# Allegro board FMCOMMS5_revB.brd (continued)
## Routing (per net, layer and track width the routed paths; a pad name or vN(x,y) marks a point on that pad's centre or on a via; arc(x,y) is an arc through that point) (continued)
RESET_A: length 113.7
  TOP w0.203: R103.2 26.49,116.87 v2(26.47,116.89)
  TOP w0.508: P401.C23 v1(86.88,107.68)
  L5_SIG w0.124: P101.25 73.17,117.4 71.85,118.72 71.85,120.62 69.38,123.1 69.03,123.1 65.16,126.97 64.19,126.97 63.74,127.42 63.74,128.52 61.62,130.63 51.69,130.63 51.53,130.47 35.09,130.47 32.91,128.3 25.78,128.3 18.41,120.93 18.41,119.63 18.42,119.62 18.42,111.49 18.96,110.96 19.74,110.96 21.47,109.23 23.82,109.23 24.55,109.96 24.55,110.41 24.43,110.52 24.43,110.81 24.55,110.92 24.55,111.54 24.43,111.65 24.43,111.94 25.23,112.74 25.23,113.88 25.71,114.36 25.71,114.9 25.56,115.05 25.56,115.5 26.25,116.18 26.25,116.67 v2(26.47,116.89)
  L6_SIG w0.124: P101.25 73.87,115.99 80.16,115.99 81.5,114.64 83.55,114.64 86.34,111.85 86.34,108.24 86.88,107.71 v1(86.88,107.68)
  BOTTOM w0.254: v2(26.47,116.89) U101.K5
RESET_B: length 141.8
  TOP w0.394: R203.2 21.56,27.3 v2(21.54,27.28)
  TOP w0.508: P402.G30 v1(80.04,47.21)
  L5_SIG w0.124: v1(80.04,47.21) 79.77,47.48 75.78,47.48 75.03,46.73 P201.25 73.43,47.39 72.2,48.62 72.2,51.47 69.65,54.02 58.78,54.02 55.18,57.62 23.01,57.62 16.21,50.81 13.27,50.81 12.43,49.97 12.43,42.7 9.25,39.53 9.25,30.65 10.6,29.3 10.6,27.52 13.27,24.85 13.27,23.66 17.75,19.18 19.45,19.18 19.88,18.75 27.84,18.75 29.73,20.64 29.73,24.1 28.47,25.36 28.03,25.36 27.91,25.24 27.62,25.24 27.51,25.36 26.89,25.36 26.78,25.24 26.36,25.24 25.56,26.04 24.39,26.04 23.95,26.49 23.58,26.49 23.53,26.45 23.46,26.37 23.1,26.37 22.19,27.28 v2(21.54,27.28)
  BOTTOM w0.254: U201.K5 v2(21.54,27.28)
RX1A_A: length 10.9
  BOTTOM w0.394: J111.1 35.56,135.21 arc(35.18,133.3) 34.1,131.69 31.81,129.39 T106.3
RX1A_B: length 10.2
  BOTTOM w0.394: J210.1 5.18,35.56 arc(6.03,35.39) 6.74,34.91 9.04,32.62 T205.3
RX1A_N_A: length 5.2
  BOTTOM w0.203: C106.2 28.14,123.32 arc(27.81,123.26) 27.54,123.08 27.18,122.72 arc(26.8,122.16) 26.68,121.5 arc(26.54,120.56) 26.13,119.69 25.96,119.52 arc(25.92,119.46) 25.9,119.38 U101.M2
RX1A_N_B: length 5.2
  BOTTOM w0.203: U201.M2 19.05,26.71 arc(18.97,26.73) 18.91,26.77 18.74,26.94 arc(17.88,27.35) 16.93,27.49 16.93,27.49 arc(16.27,27.62) 15.71,27.99 15.36,28.35 arc(15.17,28.62) 15.11,28.95 C208.2
RX1A_P_A: length 5.2
  BOTTOM w0.203: C107.2 27.53,123.89 arc(27.48,123.6) 27.31,123.35 26.93,122.97 arc(26.48,122.29) 26.32,121.5 arc(26.2,120.67) 25.85,119.92 25.71,119.78 arc(25.64,119.73) 25.57,119.72 U101.M1
RX1A_P_B: length 5.2
  BOTTOM w0.203: C209.2 14.54,28.34 arc(14.83,28.29) 15.08,28.12 15.46,27.74 arc(16.14,27.29) 16.93,27.13 arc(17.76,27.01) 18.51,26.66 18.66,26.52 arc(18.7,26.45) 18.72,26.38 U201.M1
RX1B_A: length 6.7
  BOTTOM w0.394: J103.1 17.78,132.09 C146.2 L106.1
RX1B_B: length 6.7
  BOTTOM w0.394: J203.1 6.88,17.78 C246.2 L206.1
RX1B_N_A: length 3
  BOTTOM w0.203: U101.J1 23.41,118.02 arc(23.33,118.03) 23.26,118.08 23.03,118.31 arc(22.95,118.43) 22.92,118.57 22.92,119.06 arc(22.87,119.32) 22.73,119.53 22.6,119.66 22.6,119.66 arc(22.38,120) C128.2
RX1B_N_B: length 3
  BOTTOM w0.203: U201.J1 20.41,24.22 arc(20.4,24.14) 20.35,24.08 20.12,23.84 arc(20,23.76) 19.86,23.73 19.37,23.73 arc(19.11,23.68) 18.9,23.54 18.77,23.41 arc(18.43,23.19) C228.2
RX1B_P_A: length 3
  BOTTOM w0.203: U101.H1 23.07,117.68 arc(23.06,117.76) 23.01,117.83 22.78,118.06 arc(22.62,118.3) 22.57,118.57 22.57,119.06 arc(22.54,119.18) 22.48,119.28 22.35,119.41 arc(22.01,119.63) C129.2
RX1B_P_B: length 3
  BOTTOM w0.203: U201.H1 20.75,23.88 arc(20.67,23.87) 20.6,23.82 20.37,23.59 arc(20.13,23.43) 19.86,23.38 19.37,23.38 arc(19.25,23.35) 19.15,23.29 19.02,23.16 arc(18.8,22.82) C229.2
RX1C_A: length 66.4
  TOP w0.394: v3(14.18,127.14) 14.41,127.37 15.07,127.37 T103.3
  L6_SIG w0.124: v3(14.18,127.14) 14.18,126.23 13.15,125.2 13.15,113.88 13.32,113.71 13.32,109.45 16.2,106.58 16.2,100.53 16.52,100.21 16.52,79.12 17.16,78.48 17.16,74.81 17.79,74.18 17.79,72.22 19.78,70.24 19.78,67.11 v3(20.33,66.56)
  BOTTOM w0.394: C351.2 v3(20.33,66.56)
RX1C_B: length 66.4
  TOP w0.394: T203.3 12.63,17.45 12.65,17.45 v3(12.75,17.55)
  L6_SIG w0.124: v3(18.37,66.61) 17.76,67.22 9.28,67.22 8.16,66.1 8.16,59.78 9.18,58.76 11.97,58.76 12.71,58.03 12.71,39.79 12.25,39.33 12.25,37.64 11.77,37.15 11.77,33.59 11.23,33.06 11.23,30.9 11.92,30.21 11.92,18.38 v3(12.75,17.55)
  BOTTOM w0.394: C352.2 v3(18.37,66.61)
RX1C_N_A: length 7
  TOP w0.203: C126.2 arc(19.14,121.87) 19.37,121.52 19.48,121.41 19.83,121.06 arc(19.99,120.95) 20.17,120.92 20.78,120.92 arc(21.99,120.68) 23.01,120 23.32,119.69 arc(23.32,119.68) 23.33,119.68 23.62,119.42 23.63,119.4 arc(23.84,119.26) v2(24.09,119.21)
  BOTTOM w0.254: v2(24.09,119.21) 24.15,119.15 U101.L1
RX1C_N_B: length 7
  TOP w0.203: v2(19.22,24.9) arc(19.17,24.65) 19.03,24.44 19.01,24.43 18.75,24.14 arc(18.75,24.13) 18.74,24.13 18.44,23.82 arc(17.75,22.8) 17.51,21.6 17.51,20.98 arc(17.48,20.8) 17.37,20.64 17.03,20.3 16.91,20.18 arc(16.56,19.95) C226.2
  BOTTOM w0.254: U201.L1 19.28,24.96 v2(19.22,24.9)
RX1C_P_A: length 7
  TOP w0.203: v2(23.63,118.71) arc(23.6,118.87) 23.5,119.01 23.21,119.31 23.09,119.42 arc(23.08,119.43) 23.07,119.44 22.76,119.74 arc(21.85,120.35) 20.78,120.56 20.17,120.56 arc(19.85,120.62) 19.58,120.81 19.23,121.15 19.12,121.27 arc(18.77,121.5) C127.2
  BOTTOM w0.254: v2(23.63,118.71) 23.75,118.58 U101.K1
RX1C_P_B: length 7
  TOP w0.203: v2(19.72,24.44) arc(19.56,24.41) 19.42,24.31 19.13,24.02 19.01,23.9 arc(19,23.89) 18.99,23.88 18.69,23.57 arc(18.08,22.66) 17.87,21.6 17.87,20.98 arc(17.81,20.66) 17.63,20.39 17.28,20.04 17.16,19.93 arc(16.93,19.58) C227.2
  BOTTOM w0.254: U201.K1 19.85,24.56 v2(19.72,24.44)
RX2A_A: length 11.7
  BOTTOM w0.394: T105.3 11.23,105.23 arc(9.25,103.9) 6.92,103.44 J110.1
RX2A_B: length 12.6
  BOTTOM w0.394: J211.1 35.56,6.06 arc(34.95,9.27) 33.21,12.04 T206.3
RX2A_N_A: length 5.2
  BOTTOM w0.203: 14.8,111.3 14.94,111.3 arc(15.23,111.35) 15.48,111.52 15.86,111.9 arc(16.54,112.35) 17.33,112.51 arc(18.15,112.63) 18.91,112.98 19.05,113.12 arc(19.1,113.19) 19.11,113.26 U101.A1
RX2A_N_B: length 5.2
  BOTTOM w0.203: U201.A1 25.17,19.92 arc(25.25,19.91) 25.31,19.86 25.46,19.72 arc(25.8,18.97) 25.92,18.14 arc(26.08,17.35) 26.53,16.67 26.91,16.29 arc(27.08,16.04) 27.14,15.75 C206.2
RX2A_P_A: length 5.2
  BOTTOM w0.203: 15.5,110.59 15.5,110.69 arc(15.57,111.02) 15.75,111.29 16.11,111.65 arc(16.67,112.02) 17.33,112.15 17.33,112.15 arc(18.27,112.29) 19.14,112.7 19.31,112.87 arc(19.37,112.91) 19.45,112.93 U101.A2
RX2A_P_B: length 5.2
  BOTTOM w0.203: U201.A2 25.5,20.26 arc(25.52,20.18) 25.56,20.12 25.73,19.95 arc(26.14,19.08) 26.28,18.14 26.28,18.14 arc(26.41,17.48) 26.78,16.92 27.14,16.56 arc(27.41,16.38) 27.74,16.32 27.84,16.32
RX2B_A: length 6.7
  BOTTOM w0.394: J104.1 6.88,121.22 C151.2 L108.1
RX2B_B: length 6.7
  BOTTOM w0.394: L208.1 C251.2 17.78,6.9 J204.1
RX2B_N_A: length 3
  BOTTOM w0.203: U101.F1 21.71,116.32 arc(21.63,116.34) 21.57,116.38 21.33,116.61 arc(21.1,116.77) 20.82,116.83 20.33,116.83 arc(20.21,116.85) 20.11,116.92 19.99,117.04 arc(19.76,117.38) C130.2
RX2B_N_B: length 3
  BOTTOM w0.203: U201.F1 22.11,22.52 arc(22.09,22.44) 22.05,22.38 21.82,22.15 arc(21.66,21.91) 21.6,21.63 21.6,21.14 arc(21.58,21.02) 21.51,20.92 21.39,20.8 arc(21.05,20.57) C230.2
RX2B_P_A: length 3
  BOTTOM w0.203: U101.E1 21.38,115.99 arc(21.36,116.06) 21.32,116.13 21.32,116.13 21.08,116.36 arc(20.96,116.44) 20.82,116.47 20.33,116.47 arc(20.08,116.52) 19.86,116.67 19.74,116.79 arc(19.4,117.02) C131.2
RX2B_P_B: length 3
  BOTTOM w0.203: U201.E1 22.44,22.19 arc(22.37,22.17) 22.3,22.13 22.3,22.13 22.07,21.89 arc(21.99,21.77) 21.96,21.63 21.96,21.14 arc(21.91,20.89) 21.76,20.67 21.64,20.55 21.64,20.55 arc(21.41,20.21) C231.2
RX_D0_N_A: length 85.4
  TOP w0.203: P401.H8 v1(80,88)
  L5_SIG w0.097: v2(30.43,112.93) 30.43,112.46 33.01,109.88 33.01,108.02 34.84,106.2 34.84,105.28 35.28,104.83 37.51,104.83 38.01,104.33 38.01,97.4 40.33,95.09 40.33,93.58 40.84,93.07 58.53,93.07 58.94,93.48 58.94,97.02 59.22,97.29 63.08,97.29 63.36,97.02 63.36,92.93 63.48,92.8 67.14,92.8 67.26,92.93 67.26,96.72 67.54,97 75.92,97 76.42,96.5 76.42,90.74 77.86,89.3 78.91,89.3 79.53,88.68 79.53,88.47 v1(80,88)
  BOTTOM w0.203: U101.K11 v2(30.43,112.93)
RX_D0_N_B: length 84.2
  TOP w0.203: P402.H8 v1(80,18.04)
  L5_SIG w0.097: v2(25.5,31.24) 25.64,31.24 25.87,31.47 26.33,31.47 27.95,33.09 34.29,33.09 39.7,27.68 45.64,27.68 50.04,23.28 52.29,23.28 52.74,22.83 52.74,20.91 52.87,20.78 54.24,20.78 54.36,20.91 54.36,22.01 54.68,22.33 68.8,22.33 69.36,22.89 69.36,26.95 69.64,27.22 71.21,27.22 71.49,26.95 71.49,23.07 71.59,22.97 73.13,22.97 73.22,23.06 73.22,26.41 73.98,27.18 75.97,27.18 76.47,26.68 76.47,19.97 77.09,19.34 78.93,19.34 79.54,18.73 79.54,18.5 v1(80,18.04)
  BOTTOM w0.203: U201.K11 v2(25.5,31.24)
RX_D0_P_A: length 85.4
  TOP w0.203: P401.H7 v1(78.73,88)
  L5_SIG w0.097: v2(29.86,112.36) 30.17,112.36 32.76,109.78 32.76,107.92 34.58,106.09 34.58,105.17 35.18,104.58 37.4,104.58 37.76,104.22 37.76,97.3 40.07,94.98 40.07,93.47 40.73,92.81 58.64,92.81 59.2,93.37 59.2,96.91 59.32,97.04 62.97,97.04 63.1,96.91 63.1,92.82 63.38,92.54 67.24,92.54 67.52,92.82 67.52,96.62 67.64,96.75 75.82,96.75 76.16,96.4 76.16,90.63 77.75,89.04 78.81,89.04 79.28,88.58 79.28,88.18 79.1,88 v1(78.73,88)
  BOTTOM w0.203: U101.J12 v2(29.86,112.36)
RX_D0_P_B: length 84.2
  TOP w0.203: 79.36,17.41 v1(78.73,18.04)
  L5_SIG w0.097: v2(26.07,30.67) 25.98,30.67 25.85,30.8 25.85,31.09 25.97,31.22 26.43,31.22 28.06,32.84 34.18,32.84 39.6,27.43 45.53,27.43 49.93,23.03 52.19,23.03 52.49,22.72 52.49,20.81 52.77,20.53 54.34,20.53 54.62,20.81 54.62,21.9 54.79,22.07 68.9,22.07 69.61,22.78 69.61,26.84 69.74,26.97 71.11,26.97 71.24,26.84 71.24,22.97 71.48,22.72 73.23,22.72 73.47,22.96 73.47,26.3 74.09,26.92 75.87,26.92 76.21,26.57 76.21,19.86 76.99,19.09 78.82,19.09 79.29,18.62 79.29,18.22 79.11,18.04 v1(78.73,18.04)
  BOTTOM w0.203: U201.J12 v2(26.07,30.67)
RX_D1_N_A: length 85
  TOP w0.203: 80.63,91.17 v1(80,90.54)
  L5_SIG w0.097: v2(29.86,113.49) 29.88,113.51 30.55,113.51 30.86,113.82 31.1,113.82 31.23,113.95 31.23,114.35 31.35,114.48 31.74,114.48 31.87,114.36 31.87,114.21 32.01,114.07 32.99,114.07 34.31,112.75 34.31,107.87 35.11,107.07 38.84,107.07 39.25,106.66 39.25,99.01 41.29,96.97 57.6,96.97 57.73,97.09 57.73,99.17 58.12,99.56 59.67,99.56 59.8,99.68 59.8,100.84 60.04,101.08 62.19,101.08 62.44,100.84 62.44,98.18 62.56,98.05 64.44,98.05 64.56,98.18 64.56,100.6 64.84,100.87 66.93,100.87 67.2,100.6 67.2,98.23 67.3,98.13 75.68,98.13 77.45,96.36 77.45,91.45 78.24,90.67 78.46,90.67 79.23,89.9 79.36,89.9 v1(80,90.54)
  BOTTOM w0.203: U101.K10 v2(29.86,113.49)
RX_D1_N_B: length 84.4
  TOP w0.203: 80.63,21.22 v1(80,20.58)
  L5_SIG w0.097: v2(24.94,30.67) 24.92,30.69 24.92,31.36 24.04,32.23 24.04,32.51 24.36,32.82 24.36,33.8 25.08,34.52 34.74,34.52 40.65,28.61 46,28.61 49.05,25.56 62.21,25.56 62.53,25.23 62.53,23.25 62.63,23.15 64.06,23.15 64.15,23.25 64.15,25.81 64.43,26.09 66.01,26.09 66.28,25.81 66.28,23.25 66.38,23.15 67.81,23.15 67.9,23.25 67.9,28.37 68.15,28.61 75.45,28.61 77.7,26.36 77.7,21.26 78.25,20.71 78.48,20.71 79.24,19.95 79.36,19.95 v1(80,20.58)
  BOTTOM w0.203: U201.K10 v2(24.94,30.67)
RX_D1_P_A: length 85
  TOP w0.203: 80.63,89.9 v1(80,89.27)
  L5_SIG w0.097: v2(29.3,112.93) 29.53,113.17 30.01,113.17 30.09,113.26 30.77,113.26 30.86,113.17 31.13,113.17 31.78,113.82 32.88,113.82 34.06,112.65 34.06,107.76 35.01,106.81 38.74,106.81 38.99,106.56 38.99,98.91 41.18,96.71 57.71,96.71 57.99,96.99 57.99,99.06 58.22,99.3 59.78,99.3 60.05,99.58 60.05,100.73 60.15,100.83 62.09,100.83 62.18,100.73 62.18,98.07 62.46,97.8 64.54,97.8 64.82,98.07 64.82,100.49 64.95,100.62 66.82,100.62 66.95,100.49 66.95,98.12 67.19,97.88 75.57,97.88 77.2,96.25 77.2,91.35 78.13,90.41 78.36,90.41 79.12,89.65 79.62,89.65 v1(80,89.27)
  BOTTOM w0.203: U101.J11 v2(29.3,112.93)
RX_D1_P_B: length 84.4
  TOP w0.203: 80.63,19.95 v1(80,19.31)
  L5_SIG w0.097: v2(25.5,30.11) 25.27,30.34 25.27,30.82 25.18,30.91 25.18,31.58 25.27,31.67 25.27,31.94 24.61,32.59 24.61,33.69 25.19,34.27 34.63,34.27 40.55,28.36 45.9,28.36 48.94,25.31 62.1,25.31 62.28,25.13 62.28,23.14 62.53,22.9 64.16,22.9 64.41,23.14 64.41,25.7 64.54,25.83 65.9,25.83 66.03,25.7 66.03,23.14 66.27,22.9 67.91,22.9 68.16,23.14 68.16,28.26 68.25,28.36 75.34,28.36 77.45,26.25 77.45,21.15 78.15,20.46 78.37,20.46 79.13,19.69 79.63,19.69 80.01,19.31 v1(80,19.31)
  BOTTOM w0.203: U201.J11 v2(25.5,30.11)
RX_D2_N_A: length 84.8
  TOP w0.203: P401.H11 v1(80,91.81)
  L5_SIG w0.097: v2(29.3,114.06) 29.3,114.66 30.16,115.52 33.86,115.52 35.01,114.37 35.47,113.91 35.47,110.59 35.76,110.3 38.43,110.3 38.82,109.91 38.82,108.21 39.15,107.87 40.77,107.87 41.2,107.44 41.2,100.17 41.5,99.87 54.22,99.87 54.49,99.6 54.49,97.86 54.59,97.76 56.52,97.76 56.62,97.86 56.62,101.64 57.02,102.03 69.52,102.03 69.8,101.75 69.8,98.89 69.93,98.76 72.27,98.76 72.4,98.89 72.4,101.35 72.67,101.63 74.29,101.63 74.57,101.35 74.57,100.45 79.5,95.51 79.5,92.31 v1(80,91.81)
  BOTTOM w0.203: U101.K9 v2(29.3,114.06)
RX_D2_N_B: length 84.3
  TOP w0.203: 79.36,22.49 v1(80,21.85)
  L5_SIG w0.097: v2(24.37,30.11) 23.77,30.11 22.91,30.97 22.91,34.24 24.18,35.5 27.01,35.5 27.21,35.7 35.35,35.7 41.52,29.52 50.15,29.52 50.46,29.21 50.46,26.65 50.56,26.56 63.24,26.56 63.33,26.65 63.33,29.37 63.61,29.64 65.19,29.64 65.46,29.37 65.46,27.2 65.59,27.07 66.95,27.07 67.08,27.2 67.08,29.21 67.4,29.52 71.95,29.52 72.15,29.73 72.15,30.37 72.52,30.74 75.84,30.74 76.81,29.77 76.81,28.26 79.51,25.55 79.51,22.35 79.55,22.31 79.55,22.3 v1(80,21.85)
  BOTTOM w0.203: U201.K9 v2(24.37,30.11)
RX_D2_P_A: length 84.8
  TOP w0.203: P401.H10 v1(78.73,91.81)
  L5_SIG w0.097: v1(78.73,91.81) 78.85,91.81 79.25,92.2 79.25,95.4 74.31,100.34 74.31,101.24 74.18,101.37 72.78,101.37 72.65,101.24 72.65,98.78 72.37,98.51 69.82,98.51 69.55,98.78 69.55,101.65 69.41,101.78 57.12,101.78 56.87,101.53 56.87,97.75 56.63,97.51 54.48,97.51 54.24,97.75 54.24,99.49 54.11,99.62 41.4,99.62 40.95,100.07 40.95,107.34 40.67,107.62 39.05,107.62 38.57,108.1 38.57,109.81 38.33,110.05 35.65,110.05 35.21,110.48 35.21,113.8 34.83,114.19 33.75,115.26 30.96,115.26 29.43,113.73 28.97,113.73 v2(28.73,113.49)
  BOTTOM w0.203: U101.J10 v2(28.73,113.49)
RX_D2_P_B: length 84.3
  TOP w0.203: P402.H10 v1(78.73,21.85)
  L5_SIG w0.097: v1(78.73,21.85) 79.09,21.85 79.26,22.02 79.26,25.45 76.56,28.15 76.56,29.66 75.73,30.49 72.63,30.49 72.41,30.27 72.41,29.62 72.06,29.27 67.5,29.27 67.34,29.11 67.34,27.09 67.06,26.81 65.48,26.81 65.21,27.09 65.21,29.26 65.08,29.39 63.71,29.39 63.59,29.26 63.59,26.55 63.34,26.3 50.46,26.3 50.21,26.55 50.21,29.11 50.05,29.27 41.42,29.27 35.24,35.45 27.31,35.45 27.11,35.25 24.28,35.25 23.17,34.13 23.17,31.78 23.57,31.37 23.57,31.08 23.7,30.95 23.99,30.95 24.12,30.82 24.12,30.65 24.34,30.43 24.51,30.43 24.7,30.24 24.7,29.78 v2(24.94,29.54)
  BOTTOM w0.203: U201.J10 v2(24.94,29.54)
RX_D3_N_A: length 85.4
  TOP w0.203: P401.D12 v1(85.08,93.08)
  L5_SIG w0.097: v2(28.16,115.19) 28.16,114.99 28.26,114.9 28.46,114.9 28.58,115.02 28.58,115.51 29.37,116.29 35.08,116.29 35.48,115.89 35.48,114.99 35.61,114.86 36.69,114.86 36.82,114.99 36.82,116.42 37.1,116.7 39,116.7 39.27,116.42 39.27,110.46 39.46,110.28 43.32,110.28 43.59,110 43.59,104.97 43.72,104.85 47.94,104.85 48.07,104.97 48.07,107.24 48.34,107.52 50.43,107.52 50.71,107.24 50.71,104.91 50.8,104.82 72.28,104.82 77.56,99.54 78.55,99.54 79.34,98.75 79.34,96.82 80.39,95.77 83.99,95.77 84.1,95.65 84.6,95.16 84.6,93.56 v1(85.08,93.08)
  BOTTOM w0.203: U101.K8 v2(28.16,115.19)
RX_D3_N_B: length 85.6
  TOP w0.203: P402.D12 v1(85.08,23.12)
  L5_SIG w0.097: v2(23.24,28.98) 23.36,28.98 23.47,29.08 23.47,29.24 23.32,29.39 22.92,29.39 22.14,30.18 22.14,34.71 24.23,36.79 42.15,36.79 42.9,36.04 42.9,31.42 43.4,30.92 55.76,30.92 55.89,31.05 55.89,32.07 56.25,32.43 71.77,32.43 72.54,33.2 74.27,33.2 74.55,32.93 74.55,31.69 74.77,31.47 76.06,31.47 77.94,29.58 78.57,29.58 79.35,28.8 79.35,26.86 80.4,25.81 84,25.81 84.16,25.65 84.76,25.05 84.76,23.44 v1(85.08,23.12)
  BOTTOM w0.203: U201.K8 v2(23.24,28.98)
RX_D3_P_A: length 85.4
  TOP w0.203: P401.D11 v1(83.81,93.08)
  L5_SIG w0.097: v2(28.16,114.06) 28.16,114.55 28.25,114.65 28.57,114.65 28.84,114.92 28.84,115.4 29.48,116.04 34.98,116.04 35.23,115.79 35.23,114.88 35.51,114.61 36.8,114.61 37.07,114.88 37.07,116.32 37.2,116.44 38.89,116.44 39.02,116.32 39.02,110.36 39.35,110.02 43.21,110.02 43.34,109.9 43.34,104.87 43.61,104.59 48.05,104.59 48.32,104.87 48.32,107.14 48.45,107.26 50.32,107.26 50.45,107.14 50.45,104.81 50.7,104.56 72.17,104.56 77.45,99.28 78.45,99.28 79.09,98.65 79.09,96.71 80.28,95.52 83.88,95.52 83.97,95.43 84.35,95.05 84.35,93.46 83.97,93.08 v1(83.81,93.08)
  BOTTOM w0.203: U101.J9 v2(28.16,114.06)
RX_D3_P_B: length 85.6
  TOP w0.203: 84.44,22.49 v1(83.81,23.12)
  L5_SIG w0.097: v1(83.81,23.12) 84.32,23.12 84.51,23.31 84.51,24.95 83.98,25.47 83.89,25.56 80.29,25.56 79.1,26.76 79.1,28.69 78.46,29.33 77.84,29.33 75.95,31.21 74.66,31.21 74.3,31.58 74.3,32.82 74.17,32.95 72.65,32.95 71.88,32.18 56.35,32.18 56.14,31.97 56.14,30.95 55.87,30.67 43.3,30.67 42.65,31.32 42.65,35.94 42.05,36.54 24.33,36.54 22.39,34.6 22.39,30.29 23.03,29.65 23.42,29.65 23.72,29.35 23.72,29.13 23.88,28.98 v2(24.37,28.98)
  BOTTOM w0.203: U201.J9 v2(24.37,28.98)
RX_D4_N_A: length 85.9
  TOP w0.203: v1(86.35,91.81) 85.71,92.44
  L5_SIG w0.097: v1(86.35,91.81) 85.87,92.29 85.87,99.09 85.43,99.52 82.8,99.52 82.42,99.14 82.42,97.21 82.23,97.02 80.54,97.02 80.33,97.23 80.33,99.97 79.48,100.83 77.51,100.83 72.51,105.82 51.73,105.82 51.57,105.98 51.57,107.42 49.84,109.15 46.45,109.15 45.46,110.14 45.46,112.4 44.87,112.98 40.53,112.98 40.17,113.34 40.17,116.49 39.08,117.57 29.7,117.57 28.78,116.65 28.03,116.65 27.77,116.39 27.77,115.64 27.54,115.41 27.54,114.68 v2(27.6,114.63)
  BOTTOM w0.203: U101.K7 v2(27.6,114.63)
RX_D4_N_B: length 85.8
  TOP w0.203: v1(86.35,21.85) 85.71,22.49
  L5_SIG w0.097: v2(23.81,28.41) 23.75,28.35 23.02,28.35 22.79,28.58 22.11,28.58 21.78,28.91 21.78,29.22 21.24,29.76 21.24,35.02 23.94,37.72 51.67,37.72 53.4,36 73.39,36 77.18,32.21 78.7,32.21 81.34,29.58 83.6,29.58 85.93,27.25 85.93,22.28 86.35,21.87 v1(86.35,21.85)
  BOTTOM w0.203: U201.K7 v2(23.81,28.41)
RX_D4_P_A: length 85.9
  TOP w0.203: v1(85.08,91.81) 85.71,91.17
  L5_SIG w0.097: v2(27.6,113.49) 27.6,114.12 27.93,114.44 27.93,114.8 27.84,114.88 27.84,115.35 29.81,117.32 38.98,117.32 39.91,116.39 39.91,113.24 40.42,112.73 44.77,112.73 45.2,112.3 45.2,110.04 46.34,108.9 49.74,108.9 51.32,107.32 51.32,105.88 51.63,105.57 72.41,105.57 77.4,100.57 79.37,100.57 80.08,99.87 80.08,97.12 80.44,96.76 82.33,96.76 82.67,97.1 82.67,99.03 82.91,99.27 85.33,99.27 85.61,98.98 85.61,92.34 v1(85.08,91.81)
  BOTTOM w0.203: U101.J8 v2(27.6,113.49)
RX_D4_P_B: length 85.8
  TOP w0.203: v1(85.08,21.85) 85.71,21.22
  L5_SIG w0.097: v2(24.94,28.41) 24.32,28.41 23.99,28.74 23.64,28.74 23.55,28.65 23.08,28.65 22.41,29.32 22.04,29.32 21.5,29.86 21.5,34.91 24.05,37.46 51.57,37.46 53.29,35.74 73.28,35.74 77.07,31.95 78.6,31.95 81.23,29.32 83.49,29.32 85.68,27.14 85.68,22.24 85.29,21.85 v1(85.08,21.85)
  BOTTOM w0.203: U201.J8 v2(24.94,28.41)
RX_D5_N_A: length 84.9
  TOP w0.203: P401.H14 78.77,95.66 75.81,95.66 v1(75.53,95.93)
  L5_SIG w0.097: v1(75.53,95.93) 75.32,95.71 74.46,95.71 74.13,95.38 74.13,92.05 74,91.92 66.64,91.92 66.17,91.45 66.17,88.54 66.04,88.41 64.17,88.41 64.04,88.54 64.04,91.37 63.77,91.65 61.68,91.65 61.4,91.37 61.4,88.76 61.14,88.49 53.14,88.49 52.67,88.97 52.67,91.74 52.26,92.15 38.94,92.15 33.91,97.17 33.91,105.88 31.96,107.83 31.96,109.6 31.03,110.52 28.3,113.26 27.98,113.26 27.69,112.97 27.46,112.97 26.97,113.45 26.97,114 v2(27.03,114.06)
  BOTTOM w0.203: U101.J7 v2(27.03,114.06)
RX_D5_N_B: length 85.2
  TOP w0.203: v1(75.53,25.97) 75.81,25.7 78.77,25.7 P402.H14
  L5_SIG w0.097: v1(75.53,25.97) 75.53,25.96 75.33,25.76 74.32,25.76 73.99,25.43 73.99,21.84 73.9,21.74 71.18,21.74 70.9,21.47 70.9,18.68 70.8,18.59 68.87,18.59 68.77,18.68 68.77,21.05 68.5,21.32 66.41,21.32 66.14,21.05 66.14,18.68 66.04,18.59 64.1,18.59 64.01,18.68 64.01,21.05 63.73,21.32 61.65,21.32 61.37,21.05 61.37,18.68 61.27,18.59 59.34,18.59 59.24,18.68 59.24,20.97 58.97,21.24 56.88,21.24 56.61,20.97 56.61,18.68 56.51,18.59 53.4,18.59 45.58,26.4 39.42,26.4 34.36,31.45 27.47,31.45 25.18,29.15 25.18,28.79 25.29,28.68 25.29,28.26 24.87,27.84 v2(24.37,27.84)
  BOTTOM w0.203: U201.J7 v2(24.37,27.84)
RX_D5_P_A: length 84.9
  TOP w0.203: P401.H13 79.05,95.3 75.7,95.3 v1(75.53,95.14)
  L5_SIG w0.097: v2(26.47,113.49) 26.47,113.03 26.9,112.6 27.35,112.6 27.44,112.69 27.92,112.69 28.61,112 29.19,112 31.7,109.49 31.7,107.73 33.66,105.77 33.66,97.06 38.83,91.89 52.16,91.89 52.42,91.63 52.42,88.86 53.04,88.24 61.24,88.24 61.66,88.66 61.66,91.26 61.79,91.39 63.66,91.39 63.79,91.26 63.79,88.43 64.06,88.16 66.15,88.16 66.42,88.43 66.42,91.35 66.75,91.67 74.11,91.67 74.38,91.94 74.38,95.28 74.56,95.46 75.21,95.46 v1(75.53,95.14)
  BOTTOM w0.203: U101.H8 v2(26.47,113.49)
RX_D5_P_B: length 85.2
  TOP w0.203: v1(75.53,25.18) 75.7,25.34 79.05,25.34 P402.H13
  L5_SIG w0.097: v1(75.53,25.18) 75.53,25.19 75.23,25.5 74.42,25.5 74.24,25.32 74.24,21.73 74,21.49 71.28,21.49 71.16,21.36 71.16,18.58 70.91,18.33 68.76,18.33 68.52,18.58 68.52,20.94 68.39,21.07 66.52,21.07 66.39,20.94 66.39,18.58 66.14,18.33 64,18.33 63.75,18.58 63.75,20.94 63.63,21.07 61.75,21.07 61.62,20.94 61.62,18.58 61.38,18.33 59.23,18.33 58.99,18.58 58.99,20.86 58.86,20.99 56.99,20.99 56.86,20.86 56.86,18.58 56.61,18.33 53.29,18.33 45.48,26.14 39.31,26.14 34.26,31.2 27.58,31.2 26.43,30.05 26.43,29.42 25.58,28.56 25.58,28.24 25.83,27.99 25.83,27.71 25.4,27.28 v2(24.94,27.28)
  BOTTOM w0.203: U201.H8 v2(24.94,27.28)
RX_EXT_LO_A: length 65.9
  TOP w0.394: v1(22.16,101.27) 20.7,101.27 arc(20.1,101.15) 19.59,100.8 arc(19.01,99.94) 18.81,98.92 18.81,94.85 arc(19.08,93.49) 19.85,92.33 31.08,81.1 33.61,78.56 arc(34.86,76.7) 35.3,74.51 C336.2
  L3_PWR w0.394: v2(21.75,116.89) 20.97,116.89 arc(20.16,116.73) 19.47,116.26 19.34,116.14 arc(19.05,115.74) 18.89,115.26 arc(18.79,114.76) 18.5,114.34 16.79,112.62 14.5,110.33 arc(13.96,109.53) 13.77,108.58 arc(13.96,107.62) 14.5,106.82 15.68,105.64 15.7,105.62 arc(18.06,104.04) 20.84,103.49 23.46,103.49 arc(24.02,103.25) 24.26,102.69 24.26,102.17 arc(23.99,101.53) 23.36,101.27 v1(22.16,101.27)
  BOTTOM w0.254: v2(21.75,116.89) 21.88,117.02 22.38,117.02 U101.G1
RX_EXT_LO_B: length 65.9
  TOP w0.394: v1(35.04,23.89) 35.36,24.2 arc(36.76,26.3) 37.25,28.77 arc(36.25,33.83) 33.38,38.12 30.87,40.62 arc(29.99,41.95) 29.68,43.51 29.68,55.05 arc(30.09,57.11) 31.25,58.85 33.79,61.39 arc(35.04,63.25) 35.47,65.45 C338.2
  L3_PWR w0.508: v1(35.04,23.89) 31.9,20.74 arc(29.98,19.46) 27.72,19.01 25.38,19.01 arc(23.8,19.33) 22.45,20.23 21.95,20.73 arc(21.24,21.8) v2(20.99,23.05)
  BOTTOM w0.254: U201.G1 21.26,23.32 v2(20.99,23.05)
RX_FRAME_N_A: length 85.4
  TOP w0.203: v1(85.08,89.25) 85.08,89.27 P401.D9
  L5_SIG w0.097: v2(25.9,112.93) 25.9,112.83 25.76,112.69 25.76,112.18 25.57,111.99 25.57,111.66 25.65,111.58 26.71,110.53 26.71,109.33 28.02,108.01 28.02,97.09 40.33,84.79 55.42,84.79 56.16,84.04 82.22,84.04 82.63,84.46 82.63,86.33 82.92,86.62 84.52,86.62 84.78,86.88 84.78,88.95 v1(85.08,89.25)
  BOTTOM w0.203: U101.G7 v2(25.9,112.93)
RX_FRAME_N_B: length 84.1
  TOP w0.203: P402.D9 85.08,19.31 v1(85.08,19.29)
  L5_SIG w0.097: v1(85.08,19.29) 84.87,19.08 84.87,14.68 84.28,14.09 78.34,14.09 77.07,12.82 77.07,8.03 76.79,7.75 74.71,7.75 74.43,8.03 74.43,14.35 74.11,14.68 45.58,14.68 32.05,28.21 29.79,28.21 29.1,27.52 27.9,27.52 27.34,26.95 26.99,26.95 26.9,27.04 26.29,27.04 26.19,26.94 25.73,26.94 v2(25.5,26.71)
  BOTTOM w0.203: U201.G7 v2(25.5,26.71)
RX_FRAME_P_A: length 85.4
  TOP w0.203: P401.D8 83.83,89.25 v1(83.81,89.25)
  L5_SIG w0.097: v2(26.47,112.36) 26.47,112.6 26.4,112.66 26.09,112.66 26.01,112.58 26.01,112.16 27.11,111.06 27.11,110.1 28.28,108.93 28.28,97.2 40.43,85.04 55.52,85.04 56.27,84.3 82.11,84.3 82.38,84.56 82.38,86.44 82.82,86.88 84.41,86.88 84.53,86.99 84.53,89.24 84.39,89.37 83.94,89.37 v1(83.81,89.25)
  BOTTOM w0.203: U101.G8 v2(26.47,112.36)
RX_FRAME_P_B: length 84.1
  TOP w0.203: v1(83.81,19.29) 83.83,19.29 P402.D8
  L5_SIG w0.097: v2(26.07,27.28) 26.08,27.29 26.74,27.29 27.37,27.92 28.33,27.92 28.64,28.23 28.95,28.23 29.07,28.35 29.07,28.59 29.24,28.76 29.71,28.76 30.01,28.46 32.16,28.46 45.69,14.93 74.21,14.93 74.69,14.45 74.69,8.13 74.81,8.01 76.69,8.01 76.82,8.13 76.82,12.92 78.23,14.34 84.17,14.34 84.61,14.78 84.61,19.29 84.45,19.45 83.96,19.45 v1(83.81,19.29)
  BOTTOM w0.203: U201.G8 v2(26.07,27.28)
SCL: length 124.6
  TOP w0.254: v3(36.08,59.78) 35.94,59.65 U304.15
  TOP w0.394: P401.C30 85.71,116.59 85.24,117.07 85.24,117.11 v1(85.08,117.21)
  L5_SIG w0.124: v1(85.08,117.21) 85.55,117.68 88.92,117.68 90.45,116.15 90.45,75.49 88.93,73.98 87.38,73.98 v3(86.93,73.52)
  L6_SIG w0.124: v3(36.08,59.78) 36.09,59.76 37.2,59.76 38.17,60.73 39.93,60.73 40.98,59.68 48.67,59.68 50.81,61.81 52.48,61.81 53.22,62.55 58.02,62.55 59.14,61.43 67.39,61.43 68.38,60.44 74.68,60.44 87.03,72.79 87.03,73.37 86.88,73.52 v3(86.93,73.52)
  BOTTOM w0.305: v3(86.93,73.52) 87.02,73.43 87.02,73.11 87.03,73.1 U303.6 ; R401.1 85.56,117.69 v1(85.08,117.21)
SDA: length 120.8
  TOP w0.254: v3(37.65,60.97) 37.27,60.59 37.27,59.87 36.44,59.04 U304.14
  TOP w0.394: P401.C31 85.71,117.82 86.18,117.35 86.18,117.31 v1(86.35,117.21)
  L5_SIG w0.124: v3(86.22,73.39) 86.22,73.54 87.06,74.38 88.78,74.38 89.09,74.69 90.07,75.67 90.07,113.56 89.09,114.54 89.09,116.57 88.45,117.21 v1(86.35,117.21)
  L6_SIG w0.124: v3(37.65,60.97) 37.88,61.2 40.27,61.2 41.33,60.13 48.22,60.13 51.82,63.74 72.37,63.74 73.97,62.14 75.83,62.14 86.38,72.7 86.38,73.23 v3(86.22,73.39)
  BOTTOM w0.305: R402.1 86.83,117.69 v1(86.35,117.21) ; U303.5 86.38,73.23 v3(86.22,73.39)
SPI_CLK: length 332.2
  TOP w0.203: v2(25.9,116.32) 25.9,115.8 26.49,115.21 26.49,114.01 26.85,113.65 26.85,113.34 26.65,113.14 26.65,112.72 26.85,112.52 26.85,112.2 26.65,112.01 26.65,111.64 27.14,111.15 27.35,111.15 29.02,109.48 29.32,109.48 30.16,108.64
  TOP w0.254: U302.1 23.45,67.32 23.2,67.07 R406.1 23.2,65.34 v3(23.15,65.29)
  TOP w0.394: v3(25.74,93.36) 25.74,94.22 34.07,102.55 34.07,105.14 31.55,107.66 31.14,107.66 30.16,108.64
  L6_SIG w0.124: v3(74.38,122.92) 75.04,123.58 83.78,123.58 84.44,122.92 85.35,122.92 85.99,122.29 87.31,122.29 89.19,120.4 89.19,105.28 87.23,103.31 86.17,103.31 85.03,104.46 81.74,104.46 81.14,105.07 81.14,105.55 78.21,108.47 77.38,108.47 73.82,112.03 66.23,112.03 65.03,112.03 65.01,112.05 64.33,112.73 64.13,112.93 64.13,113.44 63.58,113.98 41.28,113.98 39.41,115.86 26.36,115.86 v2(25.9,116.32) ; v2(22.11,26.71) 21.54,26.71 21.09,27.17 20.45,27.17 19.74,27.88 19.74,36.64 23.32,40.22 24.11,40.22 28.88,44.99 31.54,44.99 32.24,45.68 42.35,45.68 43.06,44.97 56.04,44.97 57.12,43.89 75.08,43.89 78.04,40.93 78.28,40.93 78.89,40.32 78.89,39.84 79.83,38.9 81.96,38.9 83.56,37.3 85.77,37.3 86.27,37.8 86.27,42.7 83.46,45.5 83.01,45.5 80.6,47.91 77.43,47.91 72.14,53.2 66.4,53.2 62.26,57.34 58.86,57.34 58.53,57.01 51.91,57.01 51.33,57.59 33.18,57.59 26.65,64.12 24.11,64.12 23.15,65.09 v3(23.15,65.29) 23.15,65.31 24.12,66.29 25.11,66.29 25.84,67.02 25.84,77.26 25.73,77.37 25.73,81.36 25.39,81.7 25.39,83 25.52,83.13 25.52,92.59 25.73,92.8 25.73,93.35 v3(25.74,93.36)
  BOTTOM w0.254: v2(22.11,26.71) U201.J5 ; v2(25.9,116.32) U101.J5
  BOTTOM w0.305: v3(74.38,122.92) SPI_CLK.1 75.19,122.93 R404.2
SPI_DI: length 315.7
  TOP w0.203: 27.2,107.49 26.85,107.84 26.85,107.99 26.65,108.19 26.65,108.56 26.85,108.76 26.85,109.13 26.28,109.69 24.15,111.82 24.15,112.9 25.72,114.47 25.72,114.82 25.2,115.34 25.2,116.75 v2(25.34,116.89)
  TOP w0.254: U302.2 23.95,67.18 23.83,67.07 23.83,65.32 v3(23.86,65.29)
  TOP w0.394: v3(26.91,101.84) 27.64,101.84 28.91,103.11 28.91,105.78 27.2,107.49
  TOP w0.508: P401.G33 v1(81.8,120.38)
  L6_SIG w0.124: v2(25.34,116.89) 25.42,116.97 25.9,116.97 26.24,117.31 26.24,117.51 26.55,117.82 27.69,117.82 28.13,118.25 39.12,118.25 42.26,115.12 64.11,115.12 65.17,114.06 71.7,114.06 72.57,113.19 75.7,113.19 76.7,112.19 78.17,112.19 78.82,111.54 78.82,111.25 79.98,110.09 80.22,110.09 81.5,108.81 82.07,108.81 83.62,107.26 86.13,107.26 86.27,107.12 87.26,107.12 87.64,107.51 87.64,114.11 86.91,114.83 84.93,114.83 83.78,115.99 81.62,115.99 81.21,116.4 81.21,119.8 v1(81.8,120.38) ; v2(21.54,26.15) 22.03,26.15 22.45,26.57 22.45,26.85 22.25,27.05 21.69,27.62 21.4,27.62 21.28,27.5 20.84,27.5 20.76,27.58 20.51,27.82 20.51,28.79 20.22,29.08 20.22,36.53 23.45,39.76 24.19,39.76 28.99,44.56 31.76,44.56 32.5,45.3 42.17,45.3 42.88,44.59 55.89,44.59 57.67,42.81 74.72,42.81 78,39.53 78.58,39.53 79.65,38.46 81.86,38.46 83.4,36.93 86.11,36.93 87.58,38.39 87.58,43.06 87.18,43.46 86.32,43.46 83.84,45.93 83.3,45.93 80.74,48.5 79.19,48.5 73.97,53.72 67.47,53.72 62.53,58.66 58.76,58.66 57.49,57.39 52.2,57.39 51.62,57.98 33.33,57.98 26.81,64.5 24.65,64.5 v3(23.86,65.29) 23.86,65.45 24.32,65.91 25.32,65.91 26.22,66.81 26.22,77.41 26.14,77.49 26.14,80.94 26.63,81.43 26.63,91.35 26.45,91.53 26.45,98.7 26.79,99.04 26.79,99.47 26.79,101.73 v3(26.91,101.84)
  BOTTOM w0.254: v2(21.54,26.15) U201.J4 ; v2(25.34,116.89) U101.J4
SPI_DO: length 315.1
  TOP w0.203: v2(27.59,116.95) 27.59,115.22 30.83,111.98 30.84,111.98 31.05,111.77
  TOP w0.394: v3(27.29,94.68) 32.9,94.68 36.19,97.97 36.19,106.63 31.05,111.77
  TOP w0.508: P401.G34 v1(81.8,121.65)
  L6_SIG w0.124: v1(81.8,121.65) 83.37,121.65 88.81,116.21 88.81,106.04 87.38,104.61 85.75,104.61 84.46,105.9 81.52,105.9 79.69,107.73 79.69,108.32 78.39,109.61 77.29,109.61 74.5,112.41 65.19,112.41 65.16,112.43 64.71,112.89 64.51,113.09 64.51,113.59 63.74,114.36 41.64,114.36 39.48,116.53 28.31,116.53 28.24,116.6 27.95,116.6 v2(27.59,116.95) ; v3(27.29,94.68) 27.29,94.53 27.48,94.34 27.48,86.99 27.75,86.71 27.75,78.54 27.48,78.26 27.48,77.3 27.45,77.27 27.45,68.62 28.19,67.89 28.19,63.81 33.64,58.36 51.93,58.36 52.43,57.85 56.85,57.85 58.12,59.12 63.03,59.12 67.75,54.39 74.33,54.39 77.17,51.55 83.71,51.55 88.59,46.66 88.59,36.68 87.71,35.8 83.26,35.8 82.06,36.99 80.21,36.99 78.79,38.41 77.95,38.41 74.01,42.35 57.44,42.35 55.66,44.13 42.78,44.13 41.99,44.93 32.83,44.93 32.06,44.16 29.24,44.16 25.08,39.99 25.08,37.87 22.69,35.48 22.69,30.44 21.48,29.23 v2(21.48,28.4)
  BOTTOM w0.254: v2(21.48,28.4) 21.48,28.41 U201.L6 ; U101.L6 27.6,116.95 v2(27.59,116.95)
SPI_ENB_A: length 86.5
  TOP w0.508: P401.G30 v1(81.8,116.57)
  L6_SIG w0.124: v2(27.03,116.32) 27.04,116.32 27.24,116.52 27.24,117.08 27.49,117.34 27.87,117.34 28.3,116.9 39.78,116.9 41.95,114.74 63.9,114.74 64.26,114.37 64.89,113.75 64.89,113.24 65.34,112.79 75.52,112.79 77.38,110.93 78.15,110.93 79.2,109.88 79.2,109.51 80.37,108.34 82,108.34 83.46,106.88 84.27,106.88 85.38,105.78 87.23,105.78 88.4,106.95 88.4,114.69 86.49,116.6 84.67,116.6 84.18,117.08 82.31,117.08 v1(81.8,116.57)
  BOTTOM w0.254: U101.K6 27.03,116.01 v2(27.03,116.32)
  BOTTOM w0.305: R403.2 v1(81.8,116.57)
SPI_ENB_B: length 173.8
  TOP w0.508: P401.G31 v1(81.8,117.84)
  L5_SIG w0.124: v1(81.8,117.84) 82.52,117.12 83.73,117.12 84.28,116.57 85.61,116.57 86.18,116 86.18,115.2 86.76,114.62 87.17,114.62 89.69,112.1 89.69,79.46 85.66,75.43 85.66,60.11 85.96,59.8 85.96,33.14 83.61,30.79 81.05,30.79 79.14,32.7 77.63,32.7 72.12,38.21 23.43,38.21 20.22,35.01 20.22,29.08 20.69,28.61 20.71,28.61 21.48,27.84 v2(22.11,27.84)
  BOTTOM w0.254: v2(22.11,27.84) 22.42,27.84 U201.K6
  BOTTOM w0.305: v1(81.8,117.84) 81.9,117.84 82.46,118.4 R405.2
SYNC_IN: length 392.6
  TOP w0.394: R211.2 23.24,24.93 v2(23.24,25.58) ; v2(24.77,115.19) 24.12,115.19 R111.2
  TOP w0.508: P401.C22 v1(86.88,106.41)
  L5_SIG w0.124: v2(23.24,25.58) 23.46,25.36 23.95,25.36 24.07,25.24 24.51,25.24 24.63,25.36 25.08,25.36 25.76,24.67 27.34,24.67 27.46,24.79 27.91,24.79 28.97,23.73 28.97,21.96 26.22,19.22 19.95,19.22 19.61,19.56 19.61,19.56 19.38,19.79 18.99,19.79 12.05,26.73 12.05,30.04 10.6,31.48 10.6,33.72 10.12,34.2 10.12,39.66 12.86,42.4 12.86,48.46 14.74,50.35 16.32,50.35 22.4,56.43 55.38,56.43 58.17,53.64 66.53,53.64 P201.24 70.89,48.53 72.09,47.33 72.09,45.96 72.46,45.59 75.38,45.59 76.04,46.25 79.91,46.25 80.56,46.9 80.56,58.11 85.1,62.65 85.1,75.55 88.99,79.45 88.99,104.3 v1(86.88,106.41) 87.54,107.07 87.54,107.83 87.66,107.95 89.14,107.95 89.27,108.08 89.27,108.97 89.14,109.09 87.49,109.09 87.36,109.22 87.36,110.11 87.49,110.23 89.17,110.23 89.29,110.36 89.29,111.25 89.17,111.38 87.85,111.38 87.23,112 86.04,112 85.86,112.18 85.86,113.17 85.66,113.37 82.51,113.37 82.39,113.5 82.39,114.61 82.51,114.74 84.47,114.74 84.6,114.87 84.6,115.75 84.47,115.88 81.25,115.88 81.01,116.12 81.01,126.95 80.81,127.15 79.46,127.15 79.26,126.95 79.26,117.25 79.13,117.13 77.68,117.13 77.55,117.25 77.55,126.96 77.43,127.08 75.67,127.08 75.55,126.96 75.55,115.94 75.16,115.55 72.61,115.55 71.97,116.19 71.97,117.9 P101.24 70.63,120.02 69.02,121.63 68.18,121.63 65.84,123.96 57.01,123.96 56.8,124.17 56.8,124.75 57.01,124.95 64.97,124.95 65.1,125.08 65.1,125.97 64.97,126.09 54.64,126.09 54.52,126.22 54.52,126.97 54.64,127.1 61.65,127.1 61.78,127.23 61.78,128.51 61.5,128.79 41.56,128.79 40.29,130.06 35.24,130.06 33.1,127.92 27.33,127.92 18.85,119.45 18.85,112.47 21.56,109.77 23.22,109.77 23.98,110.52 23.98,110.97 23.86,111.09 23.86,111.73 24.43,112.29 24.43,113.23 24.55,113.35 24.55,113.8 24.43,113.92 24.43,114.37 24.55,114.48 24.55,114.97 v2(24.77,115.19)
  BOTTOM w0.254: v2(24.77,115.19) U101.H5 ; v2(23.24,25.58) U201.H5
TX1A_A: length 9.1
  BOTTOM w0.394: J112.1 C137.2
TX1A_B: length 9.8
  BOTTOM w0.394: J212.1 9.4,53.34 arc(9.98,53.1) 10.22,52.52 C239.1
TX1A_N_A: length 6.5
  BOTTOM w0.203: 32.26,118.7 L101.2 ; 32.26,118.7 arc(32.13,118.26) L101.2 ; 32.26,118.7 arc(32.28,118.76) 32.31,118.81 arc(32.55,119.17) C122.1 ; L101.2 arc(31.08,117.58) 30.23,117.01 29.35,116.13 arc(29.31,116.06) 29.3,115.99 U101.M8
TX1A_N_B: length 5.5
  BOTTOM w0.203: U201.M8 22.44,30.11 arc(22.37,30.12) 22.3,30.17 21.43,31.04 arc(20.85,31.89) L201.2 arc(20.05,33.01) 19.56,33.33 C222.1
TX1A_P_A: length 5.6
  BOTTOM w0.203: U101.M7 28.96,116.32 arc(29.04,116.34) 29.1,116.38 29.98,117.26 arc(30.55,118.11) L103.2 31.12,119.14 arc(31.41,119.2) 31.7,119.3 arc(31.76,119.32) 31.82,119.35 arc(32.14,119.61) C123.1
TX1A_P_B: length 5.5
  BOTTOM w0.203: C223.1 18.92,32.57 arc(19.22,32.12) L203.2 arc(20.33,31.37) 21.17,30.79 22.05,29.91 arc(22.09,29.85) 22.11,29.77 U201.M7
TX1B_A: length 81
  TOP w0.394: v3(40.56,126.29) 40.56,122.95 T104.3
  L6_SIG w0.124: v3(19.67,74.33) 18.47,75.53 18.47,106.7 15.78,109.39 15.78,110.91 15.96,111.09 15.96,113.45 15.64,113.77 15.64,118.42 24.75,127.54 36.45,127.54 36.69,127.77 36.77,127.77 36.77,127.78 37.24,127.78 37.24,127.77 37.46,127.77 37.73,127.51 39.56,127.51 40.56,126.51 v3(40.56,126.29)
  BOTTOM w0.394: C349.1 v3(19.67,74.33)
TX1B_B: length 80.9
  TOP w0.394: 16.56,40.29 15.6,41.25 15.6,41.26 14.23,42.63 14.23,49.03 v3(14.74,49.54)
  L6_SIG w0.124: v3(22.39,73.32) 22.39,68.44 21.33,67.39 21.33,66.75 17.88,63.3 17.88,54.6 17.68,54.39 16.94,54.39 16.74,54.6 16.74,64 16.61,64.12 15.73,64.12 15.6,64 15.6,54.86 15.47,54.73 14.58,54.73 14.46,54.86 14.46,64.07 14.33,64.2 13.44,64.2 13.32,64.07 13.32,50.92 14.7,49.54 v3(14.74,49.54)
  BOTTOM w0.394: v3(22.39,73.32) 21.62,74.08 C350.1
TX1B_N_A: length 6.6
  TOP w0.203: C133.1 34.53,118.01 arc(34.22,117.55) L102.2 arc(33.29,116.96) 32.59,116.53 31.2,115.14 31.05,115 arc(31.01,114.93) 30.99,114.85 v2(30.99,114.62)
  BOTTOM w0.203: U101.M10 v2(30.99,114.62)
TX1B_N_B: length 6.6
  TOP w0.203: v2(23.81,31.8) 23.58,31.8 arc(23.5,31.82) 23.43,31.86 23.29,32.01 21.9,33.4 arc(21.55,34.12) L202.2 arc(20.56,35.16) C233.1
  BOTTOM w0.203: U201.M10 v2(23.81,31.8)
TX1B_P_A: length 6.6
  TOP w0.203: v2(30.43,115.19) 30.66,115.19 arc(30.73,115.21) 30.8,115.25 32.33,116.78 arc(32.76,117.49) L104.2 arc(33.37,118.42) 33.85,118.74 C132.1
  BOTTOM w0.203: v2(30.43,115.19) U101.M9
TX1B_P_B: length 6.6
  TOP w0.203: v2(23.24,31.24) 23.24,31.47 arc(23.23,31.55) 23.18,31.61 21.65,33.15 arc(20.92,33.5) L204.2 arc(19.89,34.49) 19.24,35.12
  BOTTOM w0.203: v2(23.24,31.24) U201.M9
TX2A_A: length 15.6
  BOTTOM w0.394: J113.1 12.59,85.66 arc(13.85,86.18) 14.37,87.43 C162.1
TX2A_B: length 15.2
  BOTTOM w0.394: J213.1 53.34,10.2 arc(52.51,12.21) 50.5,13.04 C211.2
TX2A_N_A: length 5.5
  BOTTOM w0.203: U101.A7 22.51,109.87 arc(22.49,109.79) 22.45,109.73 21.57,108.85 arc(20.72,108.27) L105.2 arc(19.61,107.47) 19.28,106.98 C124.1
TX2A_N_B: length 5.5
  BOTTOM w0.203: C224.1 31.45,20.09 arc(30.96,20.42) L205.2 arc(30.16,21.53) 29.58,22.38 28.71,23.26 arc(28.64,23.3) 28.56,23.32 U201.A7
TX2A_P_A: length 5.5
  BOTTOM w0.203: U101.A8 22.84,109.53 arc(22.77,109.52) 22.7,109.47 21.82,108.6 arc(21.25,107.75) L107.2 arc(20.49,106.64) 20.04,106.34 C125.1
TX2A_P_B: length 5.5
  BOTTOM w0.203: C225.1 32.09,20.85 arc(31.79,21.3) L207.2 arc(30.68,22.06) 29.83,22.63 28.96,23.51 arc(28.91,23.58) 28.9,23.65 U201.A8
TX_D0_N_A: length 84.4
  TOP w0.203: 85.71,97.52 v1(86.88,97.52)
  L6_SIG w0.097: v2(27.6,108.97) 27.36,108.73 27.36,108.21 27.19,108.04 27.19,106.84 28.11,105.92 32.46,105.92 32.83,105.55 32.83,101.77 33.07,101.53 52.56,101.53 52.84,101.25 52.84,98.67 52.56,98.39 49.23,98.39 49.1,98.27 49.1,95.88 49.23,95.76 72.18,95.76 74.2,97.77 76.62,97.77 76.99,97.4 76.99,96 77.22,95.77 84.79,95.77 85.83,96.81 86.63,96.81 86.88,97.06 v1(86.88,97.52)
  BOTTOM w0.203: U101.E12 v2(27.6,108.97)
TX_D0_N_B: length 84.2
  TOP w0.203: 85.71,27.57 v1(86.88,27.57)
  L6_SIG w0.097: v2(29.46,28.41) 29.7,28.17 31.5,28.17 31.88,28.56 31.88,31.92 32.33,32.36 47.66,32.36 47.9,32.12 47.9,28.47 48.03,28.34 51.35,28.34 51.48,28.47 51.48,31.84 51.75,32.12 54.23,32.12 54.5,31.84 54.5,28.5 54.63,28.37 61.7,28.37 61.82,28.5 61.82,30.38 62.1,30.66 64.31,30.66 64.58,30.38 64.58,28.68 64.71,28.55 65.99,28.55 66.12,28.68 66.12,30.56 66.4,30.84 69.42,30.84 69.7,30.56 69.7,28.1 69.85,27.95 76.87,27.95 79.01,25.81 84.74,25.81 85.93,27.01 86.54,27.01 86.89,27.36 86.88,27.37 v1(86.88,27.57)
  BOTTOM w0.203: U201.E12 v2(29.46,28.41)
TX_D0_P_A: length 84.4
  TOP w0.203: 85.71,96.25 v1(86.88,96.25)
  L6_SIG w0.097: v2(26.47,108.97) 26.71,108.73 26.71,108.27 26.93,108.04 26.93,106.73 28,105.66 32.35,105.66 32.58,105.44 32.58,101.66 32.96,101.27 52.46,101.27 52.58,101.15 52.58,98.78 52.46,98.65 49.12,98.65 48.85,98.37 48.85,95.78 49.12,95.5 72.28,95.5 74.3,97.52 76.51,97.52 76.74,97.3 76.74,95.9 77.12,95.52 84.9,95.52 85.94,96.56 86.58,96.56 v1(86.88,96.25)
  BOTTOM w0.203: U101.D11 v2(26.47,108.97)
TX_D0_P_B: length 84.1
  TOP w0.203: 85.71,26.3 v1(86.88,26.3)
  L6_SIG w0.097: v2(29.46,27.28) 29.7,27.52 30.16,27.52 30.57,27.92 31.61,27.92 32.14,28.45 32.14,31.81 32.43,32.11 47.55,32.11 47.65,32.01 47.65,28.37 47.93,28.09 51.45,28.09 51.73,28.37 51.73,31.74 51.86,31.86 54.12,31.86 54.25,31.74 54.25,28.39 54.52,28.12 61.8,28.12 62.08,28.39 62.08,30.27 62.2,30.4 64.2,30.4 64.33,30.27 64.33,28.57 64.61,28.3 66.1,28.3 66.38,28.57 66.38,30.45 66.5,30.58 69.32,30.58 69.44,30.45 69.44,27.99 69.74,27.7 76.76,27.7 78.9,25.56 84.84,25.56 86.04,26.75 86.42,26.75 v1(86.88,26.3)
  BOTTOM w0.203: U201.D11 v2(29.46,27.28)
TX_D1_N_A: length 84.5
  TOP w0.203: P401.H17 v1(78.2,100.06)
  L6_SIG w0.097: v1(78.2,100.06) 78.35,100.06 78.51,99.9 78.51,99.48 78.37,99.34 71.77,99.34 71.03,100.08 71.03,102.85 70.75,103.13 68.67,103.13 68.39,102.85 68.39,99.57 68.27,99.45 66.39,99.45 66.26,99.57 66.26,102.89 65.99,103.16 63.9,103.16 63.63,102.89 63.63,99.98 63.5,99.85 61.63,99.85 61.5,99.98 61.5,102.83 61.22,103.1 59.14,103.1 58.86,102.83 58.86,98.66 58.73,98.53 55.69,98.53 55.56,98.66 55.56,101.85 54.94,102.47 36.13,102.47 35.91,102.69 35.91,108.08 35.48,108.5 29.91,108.5 29.72,108.69 28.95,109.46 28.74,109.46 28.34,109.86 28.03,109.86 27.72,109.55 27.05,109.55 v2(27.03,109.53)
  BOTTOM w0.203: U101.E11 v2(27.03,109.53)
TX_D1_N_B: length 85.1
  TOP w0.203: P402.H17 v1(78.2,30.11)
  L6_SIG w0.097: v2(28.9,27.84) 28.88,27.86 28.88,28.53 28.57,28.84 28.57,29.15 28.97,29.55 28.97,29.55 30.77,31.34 30.77,33.22 31.38,33.83 34.47,33.83 35.38,34.74 38.04,34.74 39.44,33.34 57.84,33.34 58.09,33.09 58.09,29.33 58.18,29.23 59.61,29.23 59.71,29.33 59.71,33.38 59.98,33.66 62,33.66 62.25,33.41 62.25,31.63 62.34,31.53 63.26,31.53 63.36,31.63 63.36,33.41 63.6,33.66 64.73,33.66 64.98,33.41 64.98,31.63 65.08,31.53 66,31.53 66.09,31.63 66.09,33.41 66.34,33.66 67.47,33.66 67.71,33.41 67.71,31.63 67.81,31.53 68.73,31.53 68.83,31.63 68.83,33.41 69.07,33.66 71.01,33.66 71.28,33.38 71.28,30.28 71.41,30.15 73.15,30.15 73.27,30.28 73.27,32.05 73.55,32.32 75.31,32.32 75.59,32.05 75.59,29.59 75.77,29.41 78.17,29.41 78.31,29.55 78.31,30.01 78.21,30.11 v1(78.2,30.11)
  BOTTOM w0.203: U201.E11 v2(28.9,27.84)
TX_D1_P_A: length 84.5
  TOP w0.203: P401.H16 v1(78.2,98.79)
  L6_SIG w0.097: v1(78.2,98.79) 77.9,99.09 71.66,99.09 70.77,99.98 70.77,102.75 70.65,102.87 68.77,102.87 68.65,102.75 68.65,99.47 68.37,99.19 66.29,99.19 66.01,99.47 66.01,102.78 65.88,102.91 64.01,102.91 63.88,102.78 63.88,99.87 63.61,99.6 61.52,99.6 61.24,99.87 61.24,102.72 61.12,102.85 59.24,102.85 59.12,102.72 59.12,98.55 58.84,98.28 55.58,98.28 55.31,98.55 55.31,101.74 54.84,102.21 36.02,102.21 35.65,102.58 35.65,107.97 35.38,108.24 29.8,108.24 29.54,108.51 28.84,109.21 28.03,109.21 27.94,109.3 27.29,109.3 27.2,109.21 26.9,109.21 26.57,109.53 v2(25.9,109.53)
  BOTTOM w0.203: U101.D10 v2(25.9,109.53)
TX_D1_P_B: length 85.1
  TOP w0.203: P402.H16 v1(78.2,28.84)
  L6_SIG w0.097: v2(28.9,26.71) 28.9,27.38 29.22,27.71 29.22,28.01 29.14,28.1 29.14,28.75 29.23,28.84 29.23,29.44 31.02,31.23 31.02,33.12 31.48,33.58 34.58,33.58 35.48,34.48 37.94,34.48 39.33,33.09 57.74,33.09 57.83,32.99 57.83,29.22 58.08,28.98 59.72,28.98 59.96,29.22 59.96,33.28 60.09,33.4 61.9,33.4 61.99,33.31 61.99,31.53 62.24,31.28 63.37,31.28 63.61,31.53 63.61,33.31 63.71,33.4 64.63,33.4 64.73,33.31 64.73,31.53 64.97,31.28 66.1,31.28 66.35,31.53 66.35,33.31 66.44,33.4 67.36,33.4 67.46,33.31 67.46,31.53 67.7,31.28 68.83,31.28 69.08,31.53 69.08,33.31 69.18,33.4 70.9,33.4 71.03,33.28 71.03,30.17 71.3,29.9 73.25,29.9 73.53,30.17 73.53,31.94 73.65,32.07 75.2,32.07 75.33,31.94 75.33,29.49 75.66,29.15 77.9,29.15 78.21,28.84 v1(78.2,28.84)
  BOTTOM w0.203: U201.D10 v2(28.9,26.71)
TX_D2_N_A: length 84.5
  TOP w0.203: 80.63,98.79 v1(81.8,98.79)
  L6_SIG w0.097: v1(81.8,98.79) 81.8,98.42 81.51,98.14 81.13,98.14 78.39,100.88 76.98,100.88 76.31,100.21 72.12,100.21 71.84,100.48 71.84,106.46 71.57,106.73 69.48,106.73 69.21,106.46 69.21,104.16 69.08,104.03 67.2,104.03 67.08,104.16 67.08,106.5 66.8,106.78 64.72,106.78 64.44,106.5 64.44,104.12 64.31,104 62.44,104 62.31,104.12 62.31,106.37 62.04,106.64 59.95,106.64 59.68,106.37 59.68,104.03 59.44,103.79 37.01,103.79 36.88,103.91 36.88,109.09 36.53,109.44 31.28,109.44 31.11,109.61 30.27,109.61 29.28,110.59 28.01,110.59 27.92,110.68 27.36,110.68 27.03,110.35 26.05,110.35 25.9,110.5 v2(25.9,110.67)
  BOTTOM w0.203: U101.E10 v2(25.9,110.66)
TX_D2_N_B: length 85.6
  TOP w0.203: 80.63,28.84 v1(81.8,28.84)
  L6_SIG w0.097: v2(27.77,26.71) 28.08,27.02 28.08,27.84 27.75,28.17 27.75,28.73 27.84,28.82 27.84,30.17 28.24,30.57 28.24,38.31 30.5,40.57 38.8,40.57 39.33,40.04 39.33,34.94 39.67,34.59 65.79,34.59 65.88,34.69 65.88,36.74 66.16,37.02 67.74,37.02 68.01,36.74 68.01,34.69 68.11,34.59 69.54,34.59 69.63,34.69 69.63,36.7 69.91,36.97 71.65,36.97 71.93,36.7 71.93,34.2 72.17,33.96 74.77,33.96 77.81,30.92 78.4,30.92 81.02,28.3 81.28,28.3 81.8,28.82 v1(81.8,28.84)
  BOTTOM w0.203: U201.E10 27.77,26.71 v2(27.77,26.71)
TX_D2_P_A: length 84.5
  TOP w0.203: 80.63,97.52 v1(81.8,97.52)
  L6_SIG w0.097: v2(25.34,110.1) 27.13,110.1 27.46,110.43 27.82,110.43 27.9,110.34 28.59,110.34 28.8,110.13 28.8,110.13 29.58,109.35 31,109.35 31.17,109.18 36.43,109.18 36.63,108.98 36.63,103.81 36.9,103.53 59.54,103.53 59.93,103.92 59.93,106.26 60.06,106.39 61.93,106.39 62.06,106.26 62.06,104.02 62.33,103.74 64.42,103.74 64.7,104.02 64.7,106.4 64.82,106.52 66.7,106.52 66.82,106.4 66.82,104.05 67.1,103.78 69.18,103.78 69.46,104.05 69.46,106.35 69.59,106.48 71.46,106.48 71.59,106.35 71.59,100.38 72.01,99.95 76.42,99.95 77.09,100.62 78.29,100.62 81.02,97.88 81.44,97.88 v1(81.8,97.52)
  BOTTOM w0.203: U101.D9 v2(25.34,110.1)
TX_D2_P_B: length 85.6
  TOP w0.203: 80.63,27.57 v1(81.8,27.57)
  L6_SIG w0.097: v2(28.33,26.15) 28.33,27.95 28,28.27 28,28.63 28.09,28.72 28.09,29.41 28.3,29.61 28.49,29.81 28.49,38.21 30.61,40.32 38.69,40.32 39.07,39.94 39.07,34.83 39.57,34.34 65.89,34.34 66.14,34.58 66.14,36.64 66.27,36.76 67.63,36.76 67.76,36.64 67.76,34.58 68,34.34 69.64,34.34 69.89,34.58 69.89,36.59 70.01,36.72 71.54,36.72 71.67,36.59 71.67,34.1 72.06,33.71 74.66,33.71 77.7,30.67 78.3,30.67 80.92,28.05 81.32,28.05 v1(81.8,27.57)
  BOTTOM w0.203: U201.D9 v2(28.33,26.15)
TX_D3_N_A: length 84.5
  TOP w0.203: P401.D18 v1(83.28,101.33)
  L6_SIG w0.097: v2(25.34,111.23) 25.35,111.25 25.95,111.25 26.29,111.58 26.67,111.58 27,111.26 28.22,111.26 28.58,111.62 28.99,111.62 29.22,111.39 37.31,111.39 37.77,110.93 37.77,105.96 37.9,105.83 39.77,105.83 39.9,105.96 39.9,110.59 40.18,110.86 42.26,110.86 42.54,110.59 42.54,106.08 42.66,105.96 44.54,105.96 44.67,106.08 44.67,108.09 44.94,108.37 47.03,108.37 47.3,108.09 47.3,107.08 47.59,106.79 58.1,106.79 58.81,107.51 72.15,107.51 72.93,106.73 72.93,102.44 73.01,102.35 78.82,102.35 80.37,100.8 83.26,100.8 83.37,100.92 83.37,101.24 v1(83.28,101.33)
  BOTTOM w0.203: U101.E9 v2(25.34,111.23)
TX_D3_N_B: length 85.5
  TOP w0.203: P402.D18 v1(83.28,31.38)
  L6_SIG w0.097: v1(83.28,31.38) 83.29,31.38 82.82,30.9 81.16,30.9 79.66,32.4 78.2,32.4 72.21,38.39 54.05,38.39 52,36.34 49.82,36.34 49.51,36.65 49.51,38.64 49.24,38.92 47.66,38.92 47.38,38.64 47.38,36.14 47.26,36.01 45.89,36.01 45.76,36.14 45.76,39.77 44.15,41.39 29.97,41.39 27.04,38.46 27.04,30.03 26.81,29.8 26.81,29.39 27.17,29.03 27.17,27.81 26.85,27.48 26.85,27.1 27.18,26.76 27.18,26.16 v2(27.2,26.15)
  BOTTOM w0.203: U201.E9 v2(27.2,26.15)
TX_D3_P_A: length 84.5
  TOP w0.203: P401.D17 v1(83.28,100.06)
  L6_SIG w0.097: v1(83.28,100.06) 82.8,100.55 80.27,100.55 78.71,102.1 72.91,102.1 72.67,102.34 72.67,106.63 72.05,107.25 58.92,107.25 58.2,106.54 47.48,106.54 47.05,106.97 47.05,107.99 46.92,108.12 45.05,108.12 44.92,107.99 44.92,105.98 44.64,105.7 42.56,105.7 42.28,105.98 42.28,110.48 42.16,110.61 40.28,110.61 40.15,110.48 40.15,105.86 39.88,105.58 37.79,105.58 37.52,105.86 37.52,110.83 37.21,111.14 29.1,111.14 28.87,110.9 28.59,110.9 28.49,111.01 26.71,111.01 26.6,110.9 26.33,110.9 26.24,110.99 25.77,110.99 25.68,110.9 25.01,110.9 v2(24.77,110.67)
  BOTTOM w0.203: U101.D8 v2(24.77,110.67)
TX_D3_P_B: length 85.4
  TOP w0.203: P402.D17 v1(83.28,30.11)
  L6_SIG w0.097: v1(83.28,30.11) 82.74,30.65 81.06,30.65 79.56,32.14 78.09,32.14 72.1,38.14 54.15,38.14 52.1,36.08 49.72,36.08 49.26,36.54 49.26,38.54 49.13,38.66 47.76,38.66 47.64,38.54 47.64,36.03 47.36,35.76 45.79,35.76 45.51,36.03 45.51,39.67 44.04,41.14 30.07,41.14 27.3,38.36 27.3,29.91 27.53,29.68 27.53,29.4 27.43,29.3 27.43,27.52 27.53,27.41 27.53,27.14 27.44,27.05 27.44,26.58 27.53,26.49 27.53,25.82 v2(27.77,25.58)
  BOTTOM w0.203: U201.D8 v2(27.77,25.58)
TX_D4_N_A: length 84.5
  TOP w0.203: P401.C19 v1(86.88,102.6)
  L6_SIG w0.097: v1(86.88,102.6) 86.37,102.1 86.02,102.1 85.73,101.81 85.73,100.17 86.6,99.3 87.08,99.3 87.39,98.99 87.39,94.8 87.01,94.42 82.76,94.42 82.02,95.16 78.42,95.16 77.64,94.38 38.4,94.38 26.12,106.66 26.12,107 26.23,107.11 26.23,107.61 26.14,107.7 26.14,107.97 26.23,108.06 26.23,108.61 24.44,110.4 24.44,110.91 24.77,111.24 v2(24.77,111.8)
  BOTTOM w0.203: U101.E8 24.77,111.8 v2(24.77,111.8)
TX_D4_N_B: length 85.2
  TOP w0.203: P402.C19 v1(86.9,32.65)
  L6_SIG w0.097: v2(26.63,25.58) 27.19,25.58 27.52,25.25 28.03,25.25 29.82,27.04 30.37,27.04 30.46,26.95 30.73,26.95 30.82,27.04 31.32,27.04 31.43,26.93 32.33,26.93 32.94,26.33 32.94,24.28 36.93,20.29 45.37,20.29 49.63,24.55 58.59,24.55 58.68,24.64 58.68,27.2 58.95,27.48 60.53,27.48 60.81,27.2 60.81,24.64 61.02,24.42 77.65,24.42 78.44,25.21 82.04,25.21 82.78,24.47 87.02,24.47 87.4,24.84 87.4,29.04 87.09,29.35 86.61,29.35 85.57,30.39 85.57,31.88 86.03,32.34 86.6,32.34 v1(86.9,32.65)
  BOTTOM w0.203: U201.E8 v2(26.63,25.58)
TX_D4_P_A: length 84.5
  TOP w0.203: P401.C18 v1(86.88,101.33)
  L6_SIG w0.097: v1(86.88,101.33) 86.37,101.84 86.12,101.84 85.98,101.7 85.98,100.27 86.7,99.56 87.18,99.56 87.64,99.1 87.64,94.7 87.11,94.17 82.66,94.17 81.92,94.91 78.53,94.91 77.74,94.12 38.3,94.12 25.86,106.56 25.86,106.84 25.57,107.13 25.57,107.41 25.71,107.55 25.71,108.12 23.88,109.95 23.88,110.23 24.19,110.55 24.19,111.21 v2(24.2,111.23) ; v2(24.2,111.23) 24.17,111.23 v2(24.2,111.23)
  BOTTOM w0.203: U101.D7 v2(24.2,111.23)
TX_D4_P_B: length 85.2
  TOP w0.203: P402.C18 86.85,31.38 v1(86.85,31.38)
  L6_SIG w0.097: v1(86.85,31.38) 86.89,31.42 86.89,31.92 86.72,32.09 86.14,32.09 85.82,31.77 85.82,30.5 86.72,29.6 87.2,29.6 87.65,29.14 87.65,24.74 87.13,24.21 82.67,24.21 81.93,24.95 78.54,24.95 77.76,24.17 60.91,24.17 60.55,24.53 60.55,27.1 60.43,27.22 59.06,27.22 58.93,27.1 58.93,24.53 58.7,24.3 49.74,24.3 45.47,20.03 36.82,20.03 32.68,24.17 32.68,26.22 32.23,26.68 31.59,26.68 31.3,26.39 31.02,26.39 30.89,26.52 30.32,26.52 28.48,24.69 28.2,24.69 27.88,25 27.22,25 v2(27.2,25.02)
  BOTTOM w0.203: U201.D7 v2(27.2,25.02)
TX_D5_N_A: length 84.5
  TOP w0.203: P401.H20 v1(78.73,103.24)
  L6_SIG w0.097: v2(25.9,111.8) 26.14,112.03 26.6,112.03 26.85,112.28 27.22,112.28 27.46,112.03 27.73,112.03 27.97,112.27 28.35,112.27 28.59,112.03 28.87,112.03 29.14,112.31 29.4,112.31 29.68,112.03 30,112.03 30.3,112.34 30.55,112.34 30.86,112.03 42.55,112.03 44.16,110.41 48.54,110.41 48.64,110.31 48.64,108.33 48.89,108.09 51.03,108.09 51.28,108.33 51.28,110.22 51.4,110.34 53.28,110.34 53.41,110.22 53.41,108.33 53.65,108.09 55.8,108.09 56.04,108.33 56.04,110.31 56.14,110.41 58.07,110.41 58.17,110.31 58.17,108.33 58.42,108.09 60.56,108.09 60.81,108.33 60.81,110.31 60.9,110.41 62.84,110.41 62.94,110.31 62.94,108.33 63.18,108.09 65.33,108.09 65.57,108.33 65.57,110.31 65.67,110.41 67.6,110.41 67.7,110.31 67.7,108.33 67.95,108.09 69.97,108.09 70.32,108.44 70.32,110.26 70.44,110.38 71.97,110.38 72.09,110.26 72.09,108.44 72.37,108.16 73.69,108.16 73.97,107.88 73.97,105.07 74.66,104.38 79.08,104.38 79.52,103.95 79.52,103.38 79.37,103.24 v1(78.73,103.24)
  BOTTOM w0.203: U101.F8 v2(25.9,111.8)
